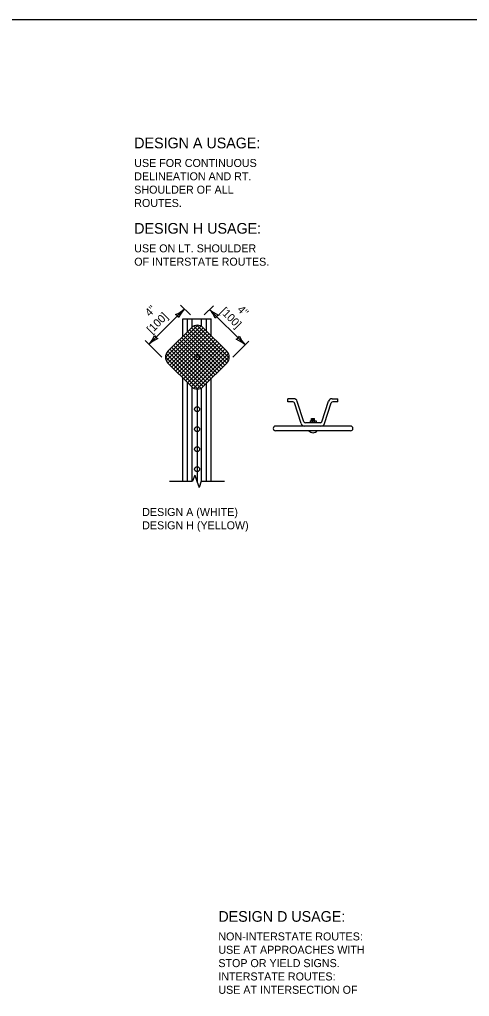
# Model space of a CAD drawing. Extents: x 49991.4 to 50021, y 49987.6 to 50011.4.
# Drawn here: x 50005.73 to 50009.1, y 49991.68 to 49999 of the extents above; entities that cross this region are included whole.
import ezdxf

# ---------------------------------------------------------------- set-up
doc = ezdxf.new("R2010")
doc.units = 0
for name, color, linetype in [('Level 1', 7, 'Continuous'), ('Level 2', 7, 'Continuous'), ('Level 3', 7, 'Continuous'), ('Level 5', 7, 'Continuous'), ('Level 6', 7, 'Continuous')]:
    doc.layers.add(name, color=color, linetype=linetype)

msp = doc.modelspace()

# ---------------------------------------------------------------- linework, layer by layer
at = {"layer": 'Level 1'}
for p, q in [((50006.9532, 49996.7563), (50007.1658, 49996.7563)), ((50006.9532, 49996.6235), (50006.9532, 49996.7563)), ((50006.9887, 49996.659), (50006.9887, 49996.7563)), ((50007.0241, 49996.6939), (50007.0241, 49996.7563)), ((50007.095, 49996.6988), (50007.095, 49996.7563)), ((50007.1305, 49996.666), (50007.1305, 49996.7563)), ((50007.1658, 49996.6307), (50007.1658, 49996.7563)), ((50006.8239, 49996.4646), (50007.0667, 49996.7074)), ((50006.8299, 49996.4413), (50007.09, 49996.7014)), ((50006.8421, 49996.4241), (50007.1073, 49996.6892)), ((50007.0189, 49996.6892), (50006.8421, 49996.5124)), ((50006.8568, 49996.4094), (50007.122, 49996.6745)), ((50006.8715, 49996.3946), (50007.1367, 49996.6598)), ((50006.8862, 49996.3799), (50007.1514, 49996.6451)), ((50006.9745, 49996.6448), (50007.2397, 49996.3797)), ((50006.9892, 49996.6595), (50007.2544, 49996.3944)), ((50007.0039, 49996.6742), (50007.2691, 49996.4091)), ((50007.0186, 49996.6889), (50007.2838, 49996.4238)), ((50007.0358, 49996.7012), (50007.2961, 49996.4409)), ((50007.059, 49996.7074), (50007.3022, 49996.4642)), ((50007.2841, 49996.5124), (50007.1073, 49996.6892)), ((50006.901, 49996.3652), (50007.1661, 49996.6304)), ((50006.901, 49996.5713), (50007.1661, 49996.3061)), ((50006.9157, 49996.3505), (50007.1808, 49996.6157)), ((50006.9157, 49996.586), (50007.1808, 49996.3208)), ((50006.9304, 49996.3358), (50007.1955, 49996.601)), ((50006.9304, 49996.6007), (50007.1955, 49996.3355)), ((50006.9451, 49996.6154), (50007.2102, 49996.3502)), ((50006.9451, 49996.3211), (50007.2102, 49996.5863)), ((50006.9598, 49996.6301), (50007.2249, 49996.3649)), ((50006.9598, 49996.3064), (50007.2249, 49996.5716)), ((50006.8299, 49996.4952), (50007.0901, 49996.2351)), ((50006.8421, 49996.5124), (50007.1073, 49996.2473)), ((50006.8568, 49996.5272), (50007.122, 49996.262)), ((50006.8715, 49996.5419), (50007.1367, 49996.2767)), ((50006.8862, 49996.5566), (50007.1514, 49996.2914)), ((50006.9745, 49996.2917), (50007.2397, 49996.5568)), ((50006.9892, 49996.277), (50007.2544, 49996.5421)), ((50007.0039, 49996.2623), (50007.2691, 49996.5274)), ((50007.0186, 49996.2476), (50007.2838, 49996.5127)), ((50007.0358, 49996.2353), (50007.2961, 49996.4956)), ((50006.8239, 49996.4718), (50007.0666, 49996.2291)), ((50006.8421, 49996.424), (50007.0189, 49996.2473)), ((50007.059, 49996.2291), (50007.3022, 49996.4723)), ((50007.1073, 49996.2473), (50007.2841, 49996.424)), ((50006.9532, 49995.5377), (50006.9532, 49996.313)), ((50006.9887, 49995.5377), (50006.9887, 49996.2775)), ((50007.1658, 49995.5377), (50007.1658, 49996.3058)), ((50007.0241, 49995.5377), (50007.0241, 49996.2426)), ((50007.095, 49995.5377), (50007.095, 49996.2377)), ((50007.1305, 49995.5377), (50007.1305, 49996.2705)), ((50007.7413, 49996.1334), (50007.7413, 49996.1569)), ((50007.784, 49996.1569), (50007.7413, 49996.1569)), ((50007.7796, 49996.1334), (50007.7413, 49996.1334)), ((50007.8613, 49995.9833), (50007.8118, 49996.1366)), ((50007.9964, 49995.9833), (50008.0461, 49996.1374)), ((50008.0737, 49996.1569), (50008.1164, 49996.1569)), ((50008.1164, 49996.1334), (50008.0781, 49996.1334)), ((50008.1164, 49996.1334), (50008.1164, 49996.1569)), ((50007.8404, 49995.9718), (50007.7908, 49996.1253)), ((50008.0173, 49995.9718), (50008.0669, 49996.1252)), ((50007.909, 49995.9898), (50007.909, 49995.9752)), ((50007.909, 49995.9898), (50007.9534, 49995.9898)), ((50007.9179, 49996.0081), (50007.9423, 49996.0081)), ((50007.9179, 49995.9898), (50007.9179, 49996.0081)), ((50007.9179, 49995.9991), (50007.9423, 49995.9991)), ((50007.9229, 49996.0034), (50007.9389, 49996.0034)), ((50007.9229, 49995.9948), (50007.9389, 49995.9948)), ((50007.9229, 49995.9898), (50007.9229, 49995.9752)), ((50007.9389, 49995.9898), (50007.9389, 49995.9752)), ((50007.9423, 49995.9898), (50007.9423, 49996.0081)), ((50007.9534, 49995.9898), (50007.9534, 49995.9752)), ((50008.2117, 49995.9515), (50007.6492, 49995.9515)), ((50008.2117, 49995.9163), (50007.6492, 49995.9163)), ((50007.9852, 49995.9752), (50007.8725, 49995.9752))]:
    msp.add_line(p, q, dxfattribs=at)
msp.add_lwpolyline([(49999.3835, 49998.9992), (50016.7501, 49998.9992), (50016.7501, 49987.7988), (49999.3835, 49987.7988)], close=True, dxfattribs=at)
for centre in [(50007.0608, 49996.4681), (50007.0608, 49996.0785), (50007.0608, 49995.9285), (50007.0608, 49995.7785), (50007.0608, 49995.6284)]:
    msp.add_circle(centre, 0.0188, dxfattribs=at)
for centre, radius, start, end in [((50007.0631, 49996.645), 0.0625, 45, 135), ((50006.8863, 49996.4682), 0.0625, 135, 225), ((50007.2399, 49996.4682), 0.0625, 315, 45), ((50007.0631, 49996.2915), 0.0625, 225, 315), ((50007.7796, 49996.1216), 0.0117, 17.88906, 90), ((50007.784, 49996.1276), 0.0293, 17.88804, 90), ((50008.0737, 49996.1276), 0.0293, 90, 160.53171), ((50008.0781, 49996.1216), 0.0117, 90, 162.11094), ((50007.8725, 49995.9869), 0.0117, 197.88895, 270), ((50007.9852, 49995.9869), 0.0117, 270, 342.11105), ((50007.6492, 49995.9339), 0.0176, 90, 270), ((50007.8682, 49995.9807), 0.0293, 197.88906, 270), ((50007.9304, 49995.9444), 0.0425, 221.39276, 318.60724), ((50007.9895, 49995.9807), 0.0293, 270, 342.11094), ((50008.2117, 49995.9339), 0.0176, 270, 90)]:
    msp.add_arc(centre, radius, start, end, dxfattribs=at)
at = {"layer": 'Level 3'}
for p, q in [((50007.012, 49996.7846), (50006.9378, 49996.8587)), ((50006.701, 49996.5653), (50006.9661, 49996.8304)), ((50007.1836, 49996.8539), (50007.1143, 49996.7846)), ((50007.1553, 49996.8256), (50007.4205, 49996.5605)), ((50006.6727, 49996.5936), (50006.7979, 49996.4682)), ((50007.3283, 49996.4682), (50007.4488, 49996.5888))]:
    msp.add_line(p, q, dxfattribs=at)
for centre, radius, start, end in [((50006.8156, 49996.994), 0.2223, 292.44521, 312.62871), ((50006.8754, 49996.7398), 0.0548, 27.12801, 62.85037), ((50007.1388, 49996.6739), 0.233, 137.81651, 157.06636), ((50006.9918, 49996.675), 0.2223, 22.46682, 42.65033), ((50007.3117, 49996.9983), 0.233, 227.83812, 247.08797), ((50007.246, 49996.7349), 0.0548, 117.14963, 152.87199), ((50006.5283, 49996.7217), 0.233, 317.81651, 337.06636), ((50006.8516, 49996.4017), 0.2223, 112.44521, 132.62871), ((50006.7917, 49996.6559), 0.0548, 207.12801, 242.85038), ((50007.3298, 49996.6511), 0.0548, 297.14963, 332.87199), ((50007.2641, 49996.3878), 0.233, 47.83812, 67.08797), ((50007.584, 49996.7111), 0.2223, 202.46682, 222.65032)]:
    msp.add_arc(centre, radius, start, end, dxfattribs=at)
at = {"layer": 'Level 5'}
msp.add_line((50007.0608, 49996.229), (50007.0608, 49995.534), dxfattribs=at)
at = {"layer": 'Level 6'}
for p, q in [((50007.0433, 49995.5834), (50007.0271, 49995.5377)), ((50007.0433, 49995.5834), (50007.0595, 49995.5377)), ((50006.8532, 49995.5377), (50007.0271, 49995.5377)), ((50007.0595, 49995.5377), (50007.0757, 49995.492)), ((50007.0919, 49995.5377), (50007.0757, 49995.492)), ((50007.0919, 49995.5377), (50007.2658, 49995.5377))]:
    msp.add_line(p, q, dxfattribs=at)

# ---------------------------------------------------------------- texts
at = {"layer": 'Level 2'}
for s, height, p in [('DESIGN A USAGE:', 0.08, (50006.59, 49998.0339)), ('USE FOR CONTINUOUS', 0.06, (50006.59, 49997.894)), ('DELINEATION AND RT.', 0.06, (50006.59, 49997.794)), ('SHOULDER OF ALL', 0.06, (50006.59, 49997.694)), ('ROUTES.', 0.06, (50006.59, 49997.594)), ('DESIGN H USAGE:', 0.08, (50006.59, 49997.3939)), ('USE ON LT. SHOULDER', 0.06, (50006.59, 49997.254)), ('OF INTERSTATE ROUTES.', 0.06, (50006.59, 49997.154)), ('DESIGN A (WHITE)', 0.06, (50006.6495, 49995.2778)), ('DESIGN H (YELLOW)', 0.06, (50006.6495, 49995.1778)), ('DESIGN D USAGE:', 0.08, (50007.2205, 49992.2359)), ('NON-INTERSTATE ROUTES:', 0.06, (50007.2205, 49992.096)), ('USE AT APPROACHES WITH', 0.06, (50007.2205, 49991.996)), ('STOP OR YIELD SIGNS.', 0.06, (50007.2205, 49991.896)), ('INTERSTATE ROUTES:', 0.06, (50007.2205, 49991.796)), ('USE AT INTERSECTION OF', 0.06, (50007.2205, 49991.696))]:
    msp.add_text(s, height=height, dxfattribs=at).set_placement(p)
for s, rotation, p in [('4"', 45, (50006.706, 49996.7683)), ('[100]', 45, (50006.7202, 49996.6411)), ('[100]', 315, (50007.2312, 49996.8063)), ('4"', 315, (50007.3584, 49996.8205))]:
    msp.add_text(s, height=0.06, rotation=rotation, dxfattribs=at).set_placement(p)

doc.saveas('drawing.dxf')
